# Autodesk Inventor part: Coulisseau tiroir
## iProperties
Author: Flavien MARTY
Shininess: 100.0
PropertySet Name: _Private Model Information
Created: 2001-10
Part Number: Coulisseau tiroir
Material: Par défaut
Document SubType Name: Modélisation
Designer: Flavien MARTY
Control State: 0
Master: False
Checked Out: False
PropertySet Name: Design Tracking Control
Density: 0.0
Volumn: 0.0
Area: 0.0
PropertySet Name: Model Information
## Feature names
1. Base1
